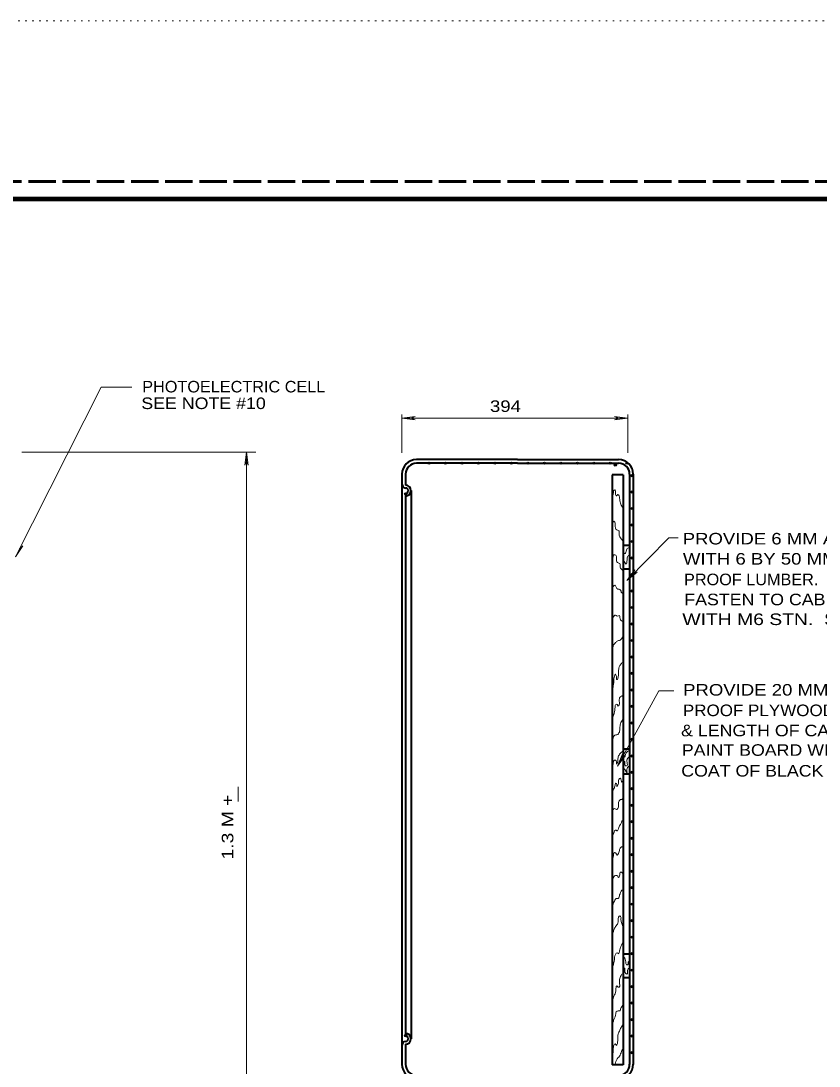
# Model space of a CAD drawing. Extents: x 312583 to 312854, y 144419 to 144597.
# Drawn here: x 312669.5 to 312721.9, y 144528 to 144596.8 of the extents above; entities that cross this region are included whole.
import ezdxf

# ---------------------------------------------------------------- set-up
doc = ezdxf.new("R2010")
doc.units = 0
doc.header["$LTSCALE"] = 0.3
doc.header["$PDMODE"] = 32
doc.header["$PDSIZE"] = 0.15
doc.linetypes.add('DOTTED', pattern=[1.5, 0.3, -1.2])
doc.linetypes.add('LONG_DASHED', pattern=[7.5, 6, -1.5])
for name, color, linetype, lineweight in [('1', 7, 'Continuous', 25), ('2', 7, 'Continuous', 13), ('63', 7, 'DOTTED', 13)]:
    doc.layers.add(name, color=color, linetype=linetype, lineweight=lineweight)

msp = doc.modelspace()

# ---------------------------------------------------------------- linework, layer by layer
at = {"layer": '1', "linetype": 'LONG_DASHED', "lineweight": 60}
msp.add_line((312851.75, 144586.2246), (312583.526, 144586.2246), dxfattribs=at)
at = {"layer": '1', "lineweight": 40}
for p, q in [((312702.1201, 144567.9344), (312695.4731, 144567.9344)), ((312702.1201, 144567.689), (312695.4731, 144567.689)), ((312702.1201, 144567.9344), (312708.7671, 144567.9344)), ((312702.1201, 144567.689), (312708.7671, 144567.689)), ((312694.5148, 144566.976), (312694.5148, 144528.1597)), ((312694.7525, 144566.976), (312694.7525, 144566.2554)), ((312708.3378, 144566.9377), (312708.3378, 144528.129)), ((312709.0585, 144566.9377), (312708.3378, 144566.9377)), ((312709.0585, 144566.9377), (312709.0585, 144528.129)), ((312709.4878, 144566.976), (312709.4878, 144528.1597)), ((312709.7255, 144566.976), (312709.7255, 144528.1597)), ((312694.7525, 144565.7264), (312694.7525, 144530.0074)), ((312695.1128, 144565.895), (312695.1128, 144529.8387)), ((312709.0815, 144562.3147), (312709.4801, 144562.3147)), ((312709.0508, 144560.7584), (312709.4878, 144560.7584)), ((312695.1128, 144559.0027), (312695.1588, 144559.0027)), ((312695.1128, 144556.9097), (312695.1588, 144556.9097)), ((312709.0508, 144548.9057), (312709.4878, 144548.9057)), ((312709.0508, 144547.2727), (312709.4878, 144547.2727)), ((312709.0508, 144535.42), (312709.4648, 144535.42)), ((312709.0508, 144533.8637), (312709.4648, 144533.8637)), ((312694.7525, 144529.4784), (312694.7525, 144528.1597)), ((312709.0585, 144528.129), (312708.3378, 144528.129))]:
    msp.add_line(p, q, dxfattribs=at)
at = {"layer": '1', "lineweight": 13}
msp.add_line((312683.7508, 144545.448), (312683.7508, 144546.4064), dxfattribs=at)
at = {"layer": '1', "lineweight": 158}
msp.add_lwpolyline([(312616.5, 144423.1446), (312616.5, 144585.0846), (312849, 144585.0846)], dxfattribs=at)
at = {"layer": '1', "lineweight": 40}
for centre, radius, start, end in [((312695.4703, 144566.9732), 0.9583, 90, 180), ((312695.4703, 144566.9732), 0.7188, 90, 180), ((312708.7681, 144566.9732), 0.9583, 0, 90), ((312708.7681, 144566.9732), 0.7188, 0, 90), ((312694.7949, 144566.3439), 0.2846, 173.88682, 261.09941), ((312694.7621, 144565.895), 0.1681, 270.98212, 93.92271), ((312694.7515, 144565.895), 0.3594, 360, 90), ((312694.7515, 144565.895), 0.3594, 360, 90), ((312694.7515, 144565.895), 0.3594, 270, 90), ((312694.7515, 144565.895), 0.3594, 270, 0), ((312694.7515, 144529.8377), 0.3594, 270, 90), ((312694.7949, 144529.3889), 0.2846, 98.90059, 186.11318), ((312694.7621, 144529.8377), 0.1681, 266.07729, 89.01788), ((312694.7515, 144529.8377), 0.3594, 270, 0), ((312695.4703, 144528.1607), 0.9583, 180, 270), ((312695.4703, 144528.1607), 0.7188, 180, 270), ((312708.7681, 144528.1607), 0.9583, 270, 0), ((312708.7681, 144528.1607), 0.7188, 270, 0)]:
    msp.add_arc(centre, radius, start, end, dxfattribs=at)
at = {"layer": '1', "lineweight": 13}
for points in [[(312708.3531, 144565.527), (312708.4221, 144565.7264), (312708.4528, 144565.9104), (312708.5141, 144565.941), (312708.5601, 144565.711), (312708.6215, 144565.55), (312708.7135, 144565.6344), (312708.7901, 144565.5577), (312708.8438, 144565.228), (312708.8898, 144565.0747), (312708.9281, 144564.9367), (312709.0125, 144564.8064), (312709.0431, 144564.6914)], [(312708.3455, 144563.503), (312708.3761, 144563.687), (312708.4528, 144563.8787), (312708.5065, 144563.8097), (312708.5371, 144563.5644), (312708.5908, 144563.365), (312708.6981, 144563.2884), (312708.7825, 144563.2577), (312708.7901, 144563.066), (312708.8438, 144562.859), (312708.9358, 144562.7287), (312708.9818, 144562.675), (312709.0585, 144562.5524)], [(312708.3531, 144561.1494), (312708.3685, 144561.341), (312708.3991, 144561.548), (312708.4451, 144561.6707), (312708.5755, 144561.6477), (312708.6291, 144561.4714), (312708.6521, 144561.203), (312708.7288, 144561.1417), (312708.8361, 144561.088), (312708.8745, 144560.858), (312709.0431, 144560.6434)], [(312708.3455, 144559.5164), (312708.4221, 144559.616), (312708.5065, 144559.6774), (312708.5601, 144559.639), (312708.6445, 144559.455), (312708.7901, 144559.4014), (312708.8975, 144559.3477), (312708.9435, 144559.2097), (312709.0431, 144559.1254)], [(312708.3455, 144557.3084), (312708.3455, 144557.3927), (312708.4375, 144557.5997), (312708.5141, 144557.707), (312708.5985, 144557.684), (312708.6751, 144557.6304), (312708.8131, 144557.6687), (312708.8438, 144557.546), (312708.8898, 144557.4004), (312709.0431, 144557.2854)], [(312708.3378, 144555.384), (312708.3685, 144555.522), (312708.4375, 144555.7444), (312708.5985, 144555.936), (312708.7595, 144556.028), (312708.8745, 144556.051), (312708.9588, 144556.1507), (312709.0431, 144556.2734)], [(312708.3455, 144552.7237), (312708.3991, 144552.946), (312708.4451, 144553.3754), (312708.4835, 144553.6974), (312708.5448, 144553.8277), (312708.6215, 144553.6667), (312708.6215, 144553.5594), (312708.6521, 144553.4597), (312708.7518, 144553.751), (312708.7518, 144553.958), (312708.7825, 144554.211), (312708.8438, 144554.3874), (312708.9205, 144554.487), (312709.0431, 144554.6327)], [(312708.3455, 144550.945), (312708.4068, 144551.06), (312708.5065, 144551.451), (312708.5295, 144551.6427), (312708.5985, 144551.8344), (312708.6828, 144551.8344), (312708.7058, 144551.7194), (312708.8055, 144551.8037), (312708.8055, 144552.0337), (312708.8131, 144552.2177), (312708.9435, 144552.3787), (312708.9895, 144552.3864), (312709.0431, 144552.394)], [(312708.3455, 144549.3887), (312708.3685, 144549.4807), (312708.4605, 144549.749), (312708.5908, 144549.8334), (312708.6521, 144549.841), (312708.8131, 144550.0097), (312708.8438, 144550.278), (312708.8898, 144550.5464), (312708.9511, 144550.715), (312709.0431, 144550.8377)], [(312708.3378, 144547.702), (312708.3991, 144547.9014), (312708.4988, 144548.162), (312708.5985, 144548.1237), (312708.6215, 144547.9014), (312708.6828, 144548.0087), (312708.7211, 144548.2617), (312708.7901, 144548.4994), (312708.8745, 144548.6067), (312709.0355, 144548.7524)], [(312708.3455, 144545.9847), (312708.3761, 144546.1227), (312708.4528, 144546.2684), (312708.5141, 144546.4524), (312708.5908, 144546.6517), (312708.6445, 144546.5597), (312708.6521, 144546.4217), (312708.7518, 144546.644), (312708.7748, 144546.8894), (312708.8668, 144546.9814), (312708.9435, 144546.8434), (312708.9588, 144546.713), (312709.0508, 144546.8204)], [(312708.3225, 144544.666), (312708.3685, 144544.804), (312708.4528, 144544.9727), (312708.5448, 144544.9727), (312708.6215, 144544.9114), (312708.7288, 144545.0264), (312708.7595, 144545.287), (312708.7901, 144545.4864), (312708.8975, 144545.5707), (312708.9818, 144545.5784), (312709.0508, 144545.7087)], [(312708.3455, 144543.0944), (312708.3761, 144543.2094), (312708.4758, 144543.4317), (312708.5525, 144543.562), (312708.5985, 144543.5697), (312708.6521, 144543.5237), (312708.7595, 144543.654), (312708.8591, 144543.907), (312708.9511, 144544.0604), (312708.9818, 144544.16), (312709.0355, 144544.1984)], [(312708.3455, 144541.6147), (312708.4145, 144541.7757), (312708.4298, 144541.975), (312708.5065, 144542.0824), (312708.5908, 144542.0517), (312708.6445, 144541.9137), (312708.7825, 144542.0977), (312708.8438, 144542.3277), (312708.9205, 144542.4197), (312708.9971, 144542.4657), (312709.0355, 144542.4427)], [(312708.3455, 144540.2347), (312708.3915, 144540.3344), (312708.4528, 144540.4954), (312708.5601, 144540.5797), (312708.7058, 144540.526), (312708.7595, 144540.4417), (312708.8285, 144540.5567), (312708.8745, 144540.7714), (312708.9205, 144540.802), (312708.9818, 144540.7867), (312709.0355, 144540.6487)], [(312708.3455, 144538.525), (312708.4145, 144538.7167), (312708.5141, 144538.9544), (312708.6138, 144539.0617), (312708.7365, 144539.077), (312708.8285, 144539.307), (312708.8898, 144539.4527), (312708.9281, 144539.5524), (312709.0508, 144539.6444)], [(312708.3455, 144536.6007), (312708.3915, 144536.7847), (312708.4528, 144536.9917), (312708.5678, 144537.214), (312708.7211, 144537.444), (312708.7365, 144537.628), (312708.8438, 144537.9194), (312708.9205, 144537.8427), (312708.9205, 144537.7354), (312708.9511, 144537.4824), (312709.0508, 144537.2294)], [(312708.3608, 144534.4387), (312708.3991, 144534.6457), (312708.4835, 144535.0367), (312708.5601, 144535.3894), (312708.6675, 144535.489), (312708.7365, 144535.4354), (312708.8438, 144535.7037), (312708.9128, 144535.903), (312709.0585, 144536.202), (312709.0278, 144536.087)], [(312708.3531, 144532.3304), (312708.4528, 144532.6524), (312708.5831, 144532.9974), (312708.6445, 144533.3194), (312708.7365, 144533.2427), (312708.7978, 144533.2427), (312708.8131, 144533.5724), (312708.8745, 144533.879), (312708.9281, 144534.0094), (312709.0508, 144534.155)], [(312708.3531, 144530.6437), (312708.3915, 144530.889), (312708.4528, 144531.1037), (312708.5831, 144531.487), (312708.6061, 144531.602), (312708.7365, 144531.6787), (312708.8361, 144531.6787), (312708.9128, 144531.8474), (312708.9511, 144531.924), (312709.0431, 144532.062)], [(312708.3531, 144528.7424), (312708.3838, 144528.8727), (312708.4145, 144529.1334), (312708.4681, 144529.44), (312708.5371, 144529.5167), (312708.6138, 144529.4017), (312708.6828, 144529.5397), (312708.7058, 144529.8387), (312708.7288, 144530.153), (312708.8438, 144530.4137), (312708.9588, 144530.636), (312709.0355, 144530.751), (312709.0508, 144530.8047)], [(312708.5371, 144528.175), (312708.5908, 144528.3437), (312708.6675, 144528.52), (312708.7748, 144528.635), (312708.8591, 144528.7577), (312708.9281, 144528.9264), (312709.0431, 144529.1947)]]:
    msp.add_spline(points, degree=3, dxfattribs=at)
at = {"layer": '1'}
for p in [(312696.2935, 144567.6967), (312697.3745, 144567.6967), (312698.4631, 144567.6967), (312699.5441, 144567.6967), (312700.6251, 144567.6967), (312701.7138, 144567.6967), (312702.7948, 144567.6967), (312703.8835, 144567.6967), (312704.9645, 144567.6967), (312706.0531, 144567.6967), (312707.1341, 144567.6967), (312708.2151, 144567.6967), (312708.5448, 144567.5817), (312709.3038, 144567.6967), (312709.5721, 144566.884), (312694.7678, 144565.6804), (312709.5721, 144565.7954), (312709.5721, 144564.7144), (312709.5721, 144563.6257), (312709.5721, 144562.5447), (312709.5721, 144561.456), (312709.5721, 144560.375), (312709.5721, 144559.294), (312709.5721, 144558.2054), (312709.5721, 144557.1244), (312709.5721, 144556.0357), (312709.5721, 144554.9547), (312709.5721, 144553.8737), (312709.5721, 144552.785), (312709.5721, 144551.704), (312709.5721, 144550.6154), (312709.5721, 144549.5344), (312709.5721, 144548.4457), (312709.5721, 144547.3647), (312709.5721, 144546.2837), (312709.5721, 144545.195), (312709.5721, 144544.114), (312709.5721, 144543.0254), (312709.5721, 144541.9444), (312709.5721, 144540.8557), (312709.5721, 144539.7747), (312709.5721, 144538.6937), (312709.5721, 144537.605), (312709.5721, 144536.524), (312709.5721, 144535.4354), (312709.5721, 144534.3544), (312709.5721, 144533.2657), (312709.5721, 144532.1847), (312709.5721, 144531.1037), (312694.7678, 144530.0534), (312709.5721, 144530.015), (312709.5721, 144528.934)]:
    msp.add_point(p, dxfattribs=at)
at = {"layer": '2'}
for p, q in [((312694.5148, 144568.379), (312694.5148, 144570.9014)), ((312694.5148, 144570.6637), (312695.3811, 144570.771)), ((312695.3811, 144570.771), (312695.1051, 144570.6637)), ((312708.4988, 144570.771), (312708.7748, 144570.6637)), ((312709.3651, 144570.6637), (312708.4988, 144570.771)), ((312709.3651, 144568.379), (312709.3651, 144570.9014)), ((312694.5148, 144570.6637), (312709.3651, 144570.6637)), ((312694.5148, 144570.6637), (312695.3811, 144570.5564)), ((312695.3811, 144570.5564), (312695.1051, 144570.6637)), ((312708.4988, 144570.5564), (312708.7748, 144570.6637)), ((312709.3651, 144570.6637), (312708.4988, 144570.5564)), ((312669.5138, 144568.425), (312684.9161, 144568.425)), ((312684.2875, 144568.425), (312684.1801, 144567.5587)), ((312684.2875, 144568.425), (312684.3948, 144567.5587)), ((312684.1801, 144567.5587), (312684.2875, 144567.8347)), ((312684.3948, 144567.5587), (312684.2875, 144567.8347)), ((312669.0998, 144561.548), (312669.5828, 144562.2687)), ((312669.5828, 144562.2687), (312669.3681, 144562.0694)), ((312709.3038, 144559.9917), (312709.8405, 144560.6817)), ((312709.3038, 144559.9917), (312709.9938, 144560.5284)), ((312709.8405, 144560.6817), (312709.7178, 144560.4057)), ((312709.9938, 144560.5284), (312709.7178, 144560.4057)), ((312711.4198, 144552.7237), (312708.6905, 144547.771)), ((312711.4198, 144552.7237), (312712.4037, 144552.7237)), ((312708.6905, 144547.771), (312709.0125, 144548.5837)), ((312708.6905, 144547.771), (312709.2041, 144548.4764)), ((312709.0125, 144548.5837), (312708.9741, 144548.2847)), ((312709.2041, 144548.4764), (312708.9741, 144548.2847))]:
    msp.add_line(p, q, dxfattribs=at)
for points in [[(312669.0998, 144561.548), (312674.7348, 144572.703), (312676.7588, 144572.703)], [(312684.2875, 144487.0664), (312684.2875, 144521.5894), (312684.2875, 144568.425)], [(312709.3038, 144559.9917), (312712.0638, 144562.7977), (312712.6839, 144562.7977)]]:
    msp.add_lwpolyline(points, dxfattribs=at)
for points in [[(312709.0815, 144561.594), (312709.1275, 144561.7857), (312709.1888, 144561.7474), (312709.2501, 144561.8317), (312709.3345, 144562.0847), (312709.5031, 144562.1767)], [(312709.0968, 144561.042), (312709.1428, 144561.2337), (312709.1735, 144561.1724), (312709.2501, 144561.0574), (312709.3191, 144561.341), (312709.3805, 144561.5787), (312709.4571, 144561.64)], [(312709.0508, 144548.6297), (312709.1045, 144548.4687), (312709.1658, 144548.3614), (312709.2041, 144548.461), (312709.2195, 144548.5454), (312709.2655, 144548.645), (312709.3421, 144548.7294), (312709.4188, 144548.783), (312709.4801, 144548.7907)], [(312709.0508, 144547.978), (312709.1045, 144548.0777), (312709.1658, 144548.0854), (312709.1735, 144547.978), (312709.1811, 144547.863), (312709.2195, 144547.794), (312709.2885, 144547.794), (312709.3421, 144547.8477), (312709.3345, 144547.9244), (312709.3345, 144547.978), (312709.3115, 144548.0777), (312709.3115, 144548.185), (312709.3651, 144548.2924), (312709.4495, 144548.392), (312709.4801, 144548.415)], [(312709.0738, 144547.5947), (312709.1351, 144547.587), (312709.1735, 144547.5564), (312709.2118, 144547.4874), (312709.2501, 144547.4184), (312709.2731, 144547.3647), (312709.2885, 144547.3494), (312709.3038, 144547.3494), (312709.3115, 144547.4337), (312709.3115, 144547.4644), (312709.3115, 144547.5487), (312709.3498, 144547.679), (312709.3881, 144547.7174), (312709.4495, 144547.7557), (312709.4878, 144547.748)], [(312709.0585, 144535.1287), (312709.1351, 144535.19), (312709.1965, 144535.075), (312709.2348, 144534.891), (312709.2808, 144534.7147), (312709.3881, 144534.7454), (312709.4188, 144534.9064), (312709.4648, 144534.9217)], [(312709.0738, 144534.385), (312709.1198, 144534.4924), (312709.1658, 144534.4617), (312709.1658, 144534.3544), (312709.1811, 144534.2317), (312709.2195, 144534.1474), (312709.3115, 144534.086), (312709.3575, 144534.2317), (312709.3881, 144534.431), (312709.4648, 144534.4924)]]:
    msp.add_spline(points, degree=3, dxfattribs=at)
at = {"layer": '63'}
msp.add_line((312601.2, 144596.7846), (312853.5, 144596.7846), dxfattribs=at)

# ---------------------------------------------------------------- texts
at = {"layer": '2'}
for s, width, p in [('PHOTOELECTRIC CELL', 1.05, (312677.4409, 144572.3494)), ('SEE NOTE #10', 1.15, (312677.3767, 144571.2565)), ('394 ', 1.2, (312700.3065, 144571.0654)), ('PROVIDE 6 MM AIR SPACE', 1.2, (312712.9784, 144562.3513)), ('WITH 6 BY 50 MM WEATHER-', 1.2, (312712.9931, 144561.0262)), ('PROOF LUMBER.', 1.05, (312713.0674, 144559.6704)), ('FASTEN TO CABINET', 1.15, (312713.0839, 144558.3517)), ('WITH M6 STN.  STL.  BOLTS.', 1.25, (312712.9571, 144557.0506)), ('PROVIDE 20 MM THK.  WEATHER-', 1.2, (312713.0068, 144552.4101)), ('PROOF PLYWOOD FULL WIDTH', 1.1, (312712.9926, 144551.0607)), ('& LENGTH OF CABINET.', 1.15, (312712.8716, 144549.7343)), ('PAINT BOARD WITH ONE', 1.15, (312712.9218, 144548.4498)), ('COAT OF BLACK PAINT.', 1.15, (312712.8821, 144547.0863))]:
    msp.add_text(s, height=0.76, dxfattribs=dict(at, width=width)).set_placement(p)
at = {"layer": '2', "width": 1.25}
msp.add_text('1.3 M +', height=0.76, rotation=90, dxfattribs=at).set_placement((312683.4298, 144541.63))

doc.saveas('drawing.dxf')
